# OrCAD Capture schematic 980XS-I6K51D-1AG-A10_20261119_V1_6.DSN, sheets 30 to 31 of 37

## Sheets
30 P0032_S3_USB/AUD/FLASH/XTAL: size A1
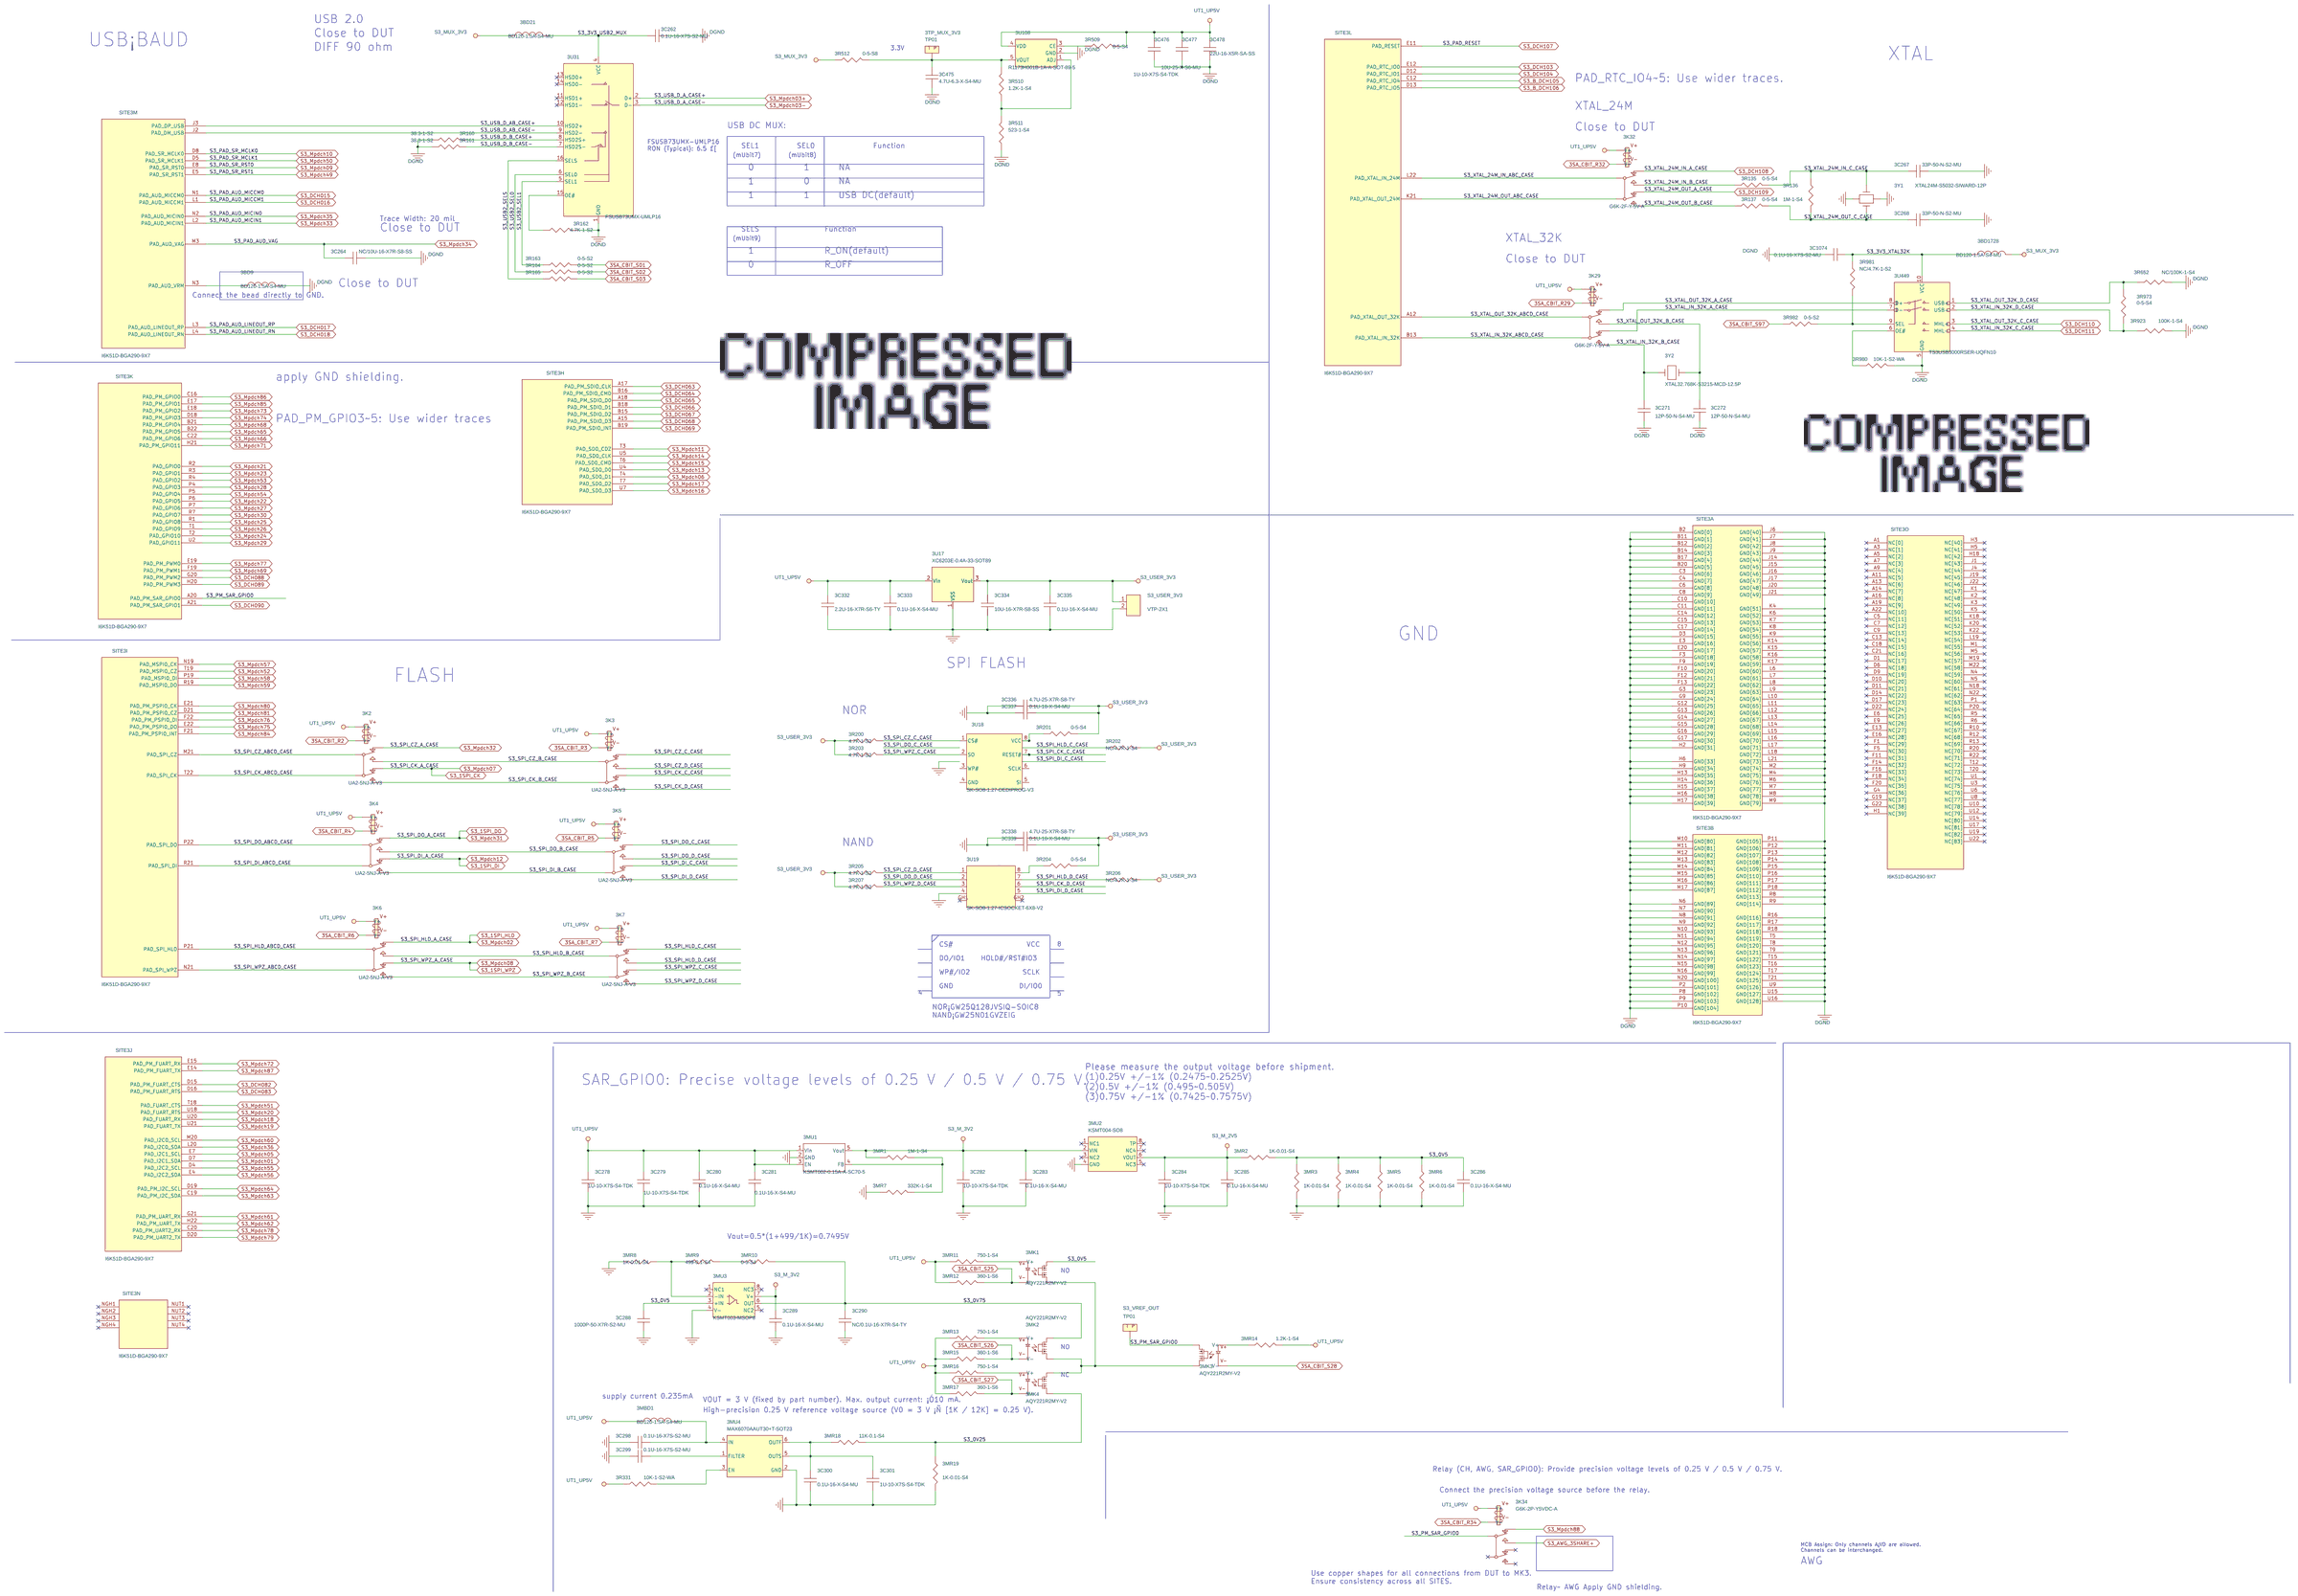
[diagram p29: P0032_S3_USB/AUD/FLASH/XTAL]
31 P0012_S1_USB/AUD/FLASH/XTAL: size A1
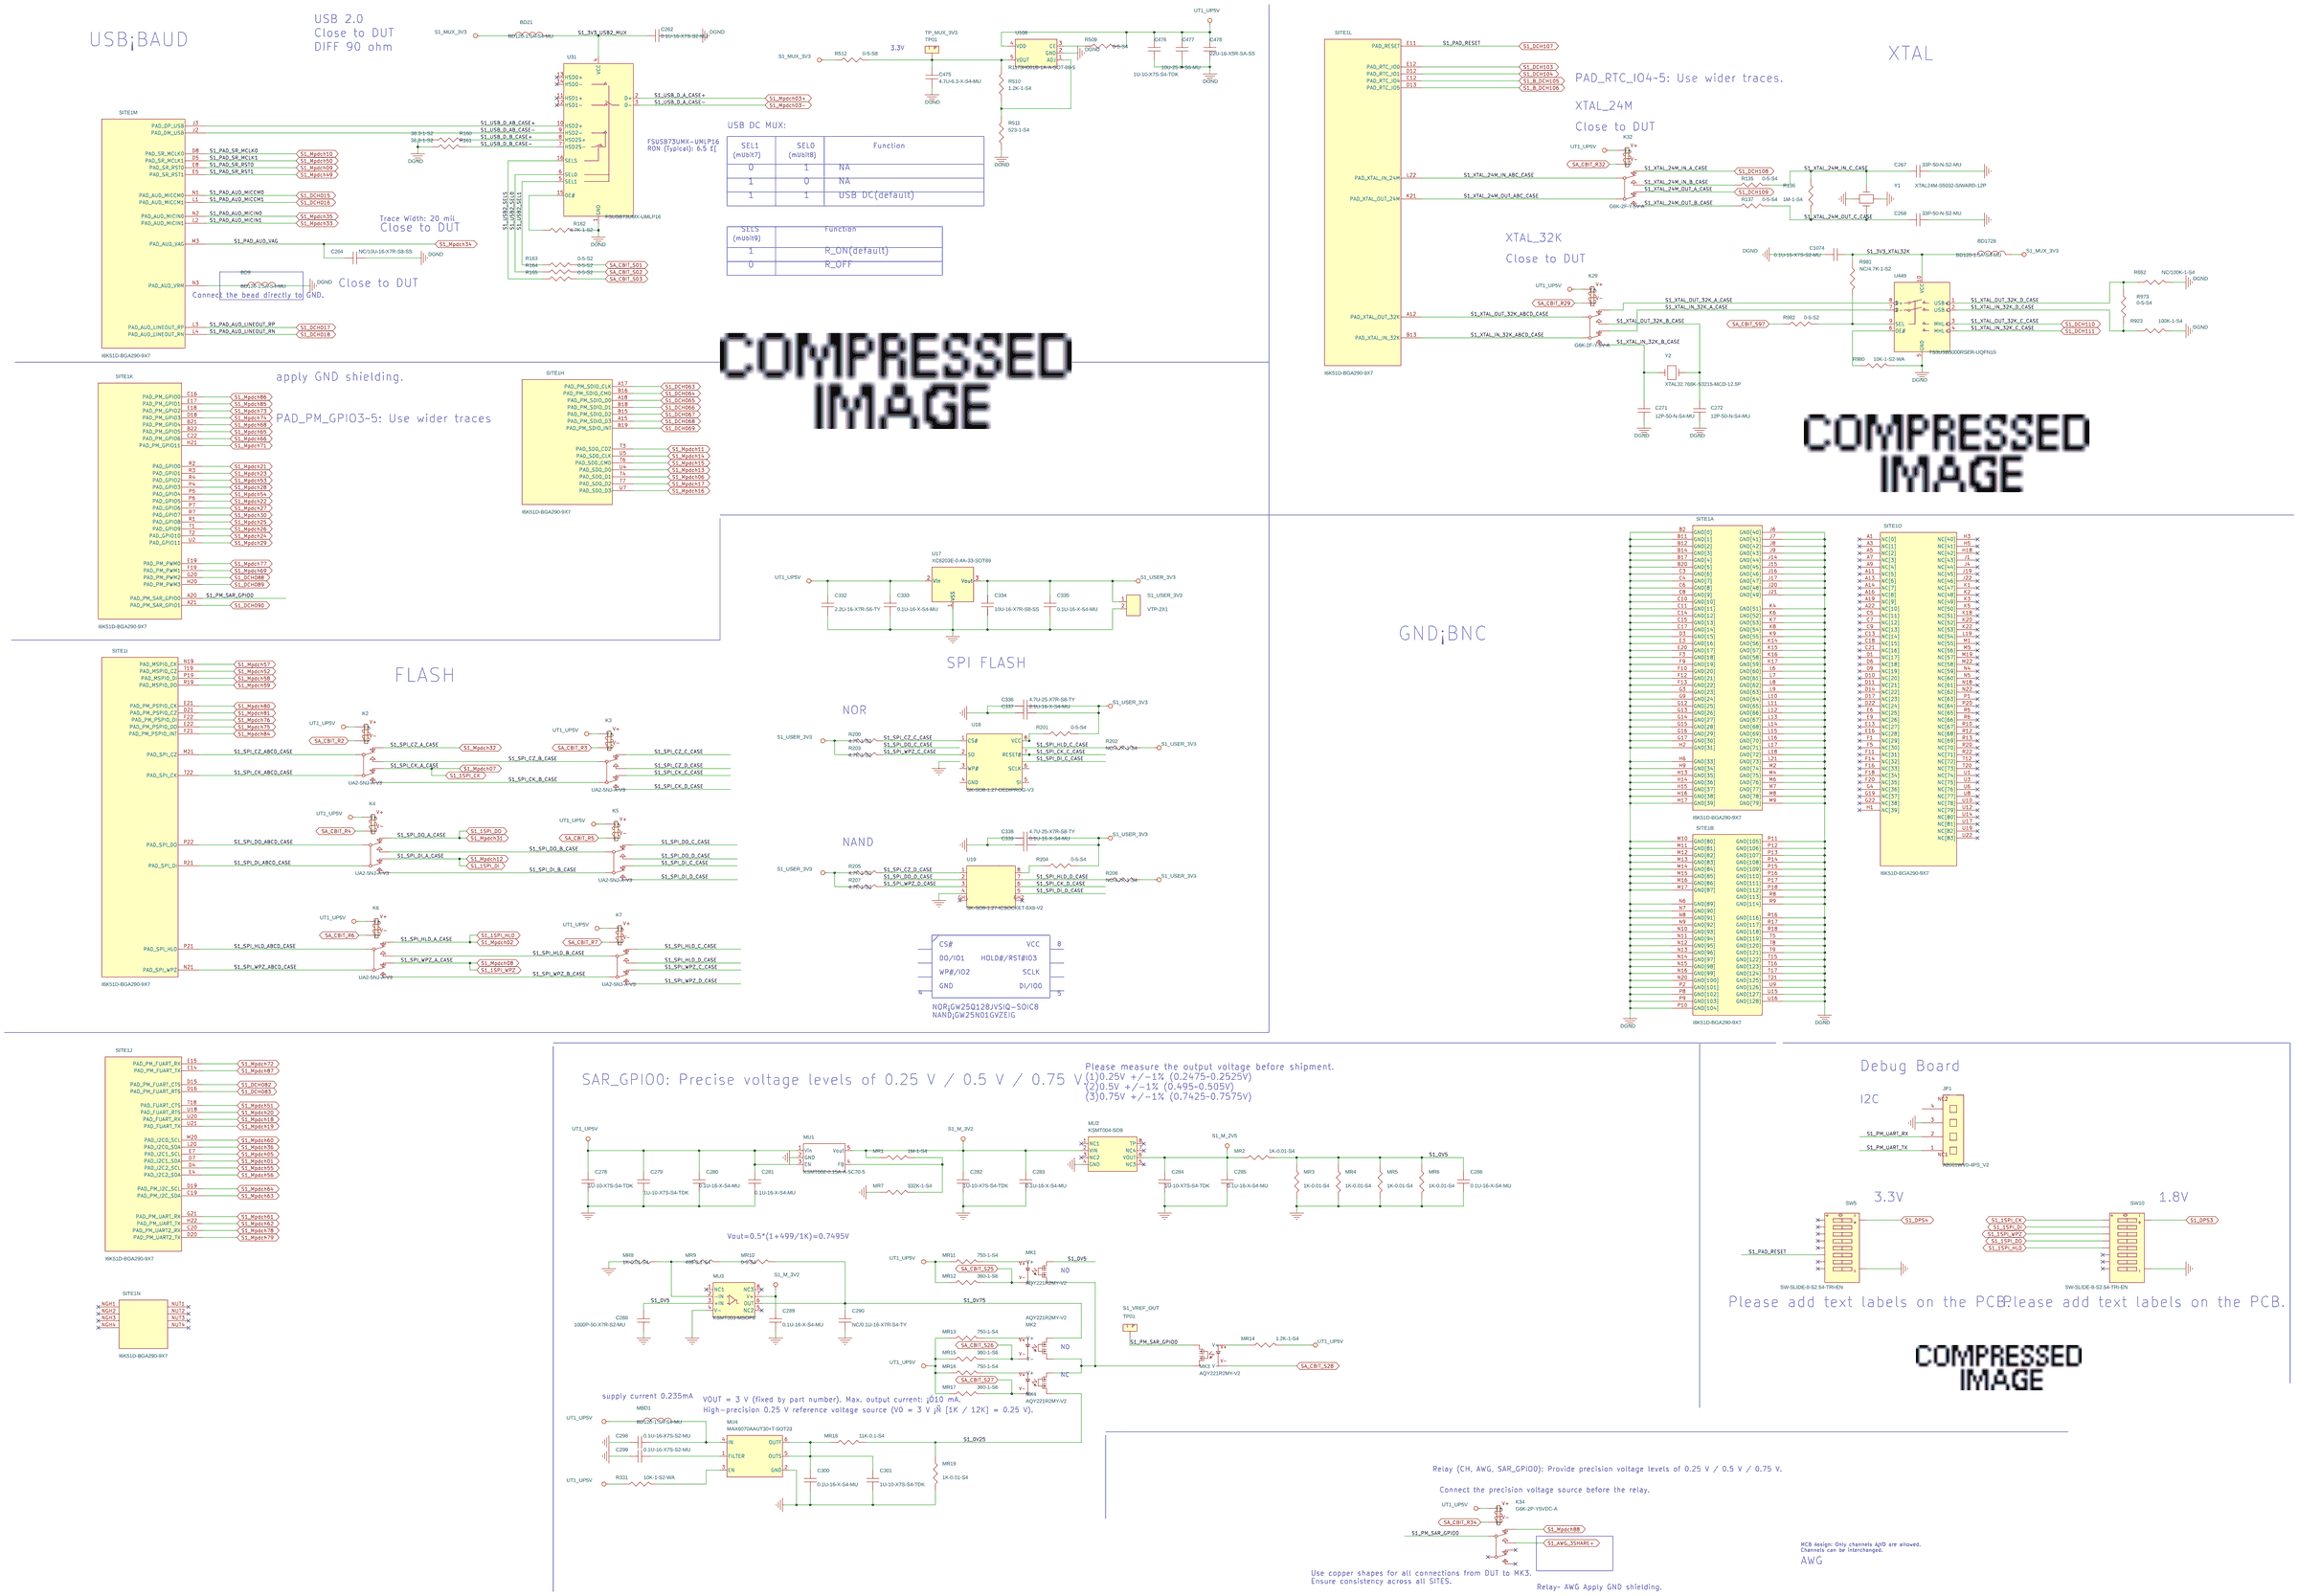
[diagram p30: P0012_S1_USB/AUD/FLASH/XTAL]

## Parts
sheet P0011_S1_POWER
SITE1  I6K51D-BGA290-9X7  [SK_TFBGA7X9_290P_0P4MM_JG]  (sections A,B,C,D,E,F,G,H,I,J,K,L,M,N,O)
sheet P0012_S1_USB/AUD/FLASH/XTAL
BD9  BD120-1.5A-S4-MU  [FB0402]
BD21  BD120-1.5A-S4-MU  [FB0402]
BD1728  BD120-1.5A-S4-MU  [FB0402]
C262  0.1U-16-X7S-S2-MU  [C0201]
C264  NC/10U-16-X7R-S8-SS  [C0805]
C267  33P-50-N-S2-MU  [C0201]
C268  33P-50-N-S2-MU  [C0201]
C271  12P-50-N-S4-MU  [C0402]
C272  12P-50-N-S4-MU  [C0402]
C278  1U-10-X7S-S4-TDK  [C0402]
C279  1U-10-X7S-S4-TDK  [C0402]
C280  0.1U-16-X-S4-MU  [C0402]
C281  0.1U-16-X-S4-MU  [C0402]
C282  1U-10-X7S-S4-TDK  [C0402]
C283  0.1U-16-X-S4-MU  [C0402]
C284  1U-10-X7S-S4-TDK  [C0402]
C285  0.1U-16-X-S4-MU  [C0402]
C286  0.1U-16-X-S4-MU  [C0402]
C288  1000P-50-X7R-S2-MU  [C0201]
C289  0.1U-16-X-S4-MU  [C0402]
C290  NC/0.1U-16-X7R-S4-TY  [C0402]
C298  0.1U-16-X7S-S2-MU  [C0201]
C299  0.1U-16-X7S-S2-MU  [C0201]
C300  0.1U-16-X-S4-MU  [C0402]
C301  1U-10-X7S-S4-TDK  [C0402]
C332  2.2U-16-X7R-S6-TY  [C0603]
C333  0.1U-16-X-S4-MU  [C0402]
C334  10U-16-X7R-S8-SS  [C0805]
C335  0.1U-16-X-S4-MU  [C0402]
C336  4.7U-25-X7R-S8-TY  [C0805]
C337  0.1U-16-X-S4-MU  [C0402]
C338  4.7U-25-X7R-S8-TY  [C0805]
C339  0.1U-16-X-S4-MU  [C0402]
C475  4.7U-6.3-X-S4-MU  [C0402]
C476  1U-10-X7S-S4-TDK  [C0402]
C477  10U-25-X-S6-MU  [C0603]
C478  22U-16-X5R-SA-SS  [C1206]
C1074  0.1U-16-X7S-S2-MU  [C0201_MINI]
JP1  A2001WV0-4PS_V2  [CONN_S4X1_2MM_JWT]
K2  UA2-5NJ-A-V3  [RL_NECUA2_5V_V3]
K3  UA2-5NJ-A-V3  [RL_NECUA2_5V_V3]
K4  UA2-5NJ-A-V3  [RL_NECUA2_5V_V3]
K5  UA2-5NJ-A-V3  [RL_NECUA2_5V_V3]
K6  UA2-5NJ-A-V3  [RL_NECUA2_5V_V3]
K7  UA2-5NJ-A-V3  [RL_NECUA2_5V_V3]
K29  G6K-2F-Y-5V-A  [RL_G6K2F-Y_5V_OMRON]
K32  G6K-2F-Y-5V-A  [RL_G6K2F-Y_5V_OMRON]
K34  G6K-2P-Y5VDC-A  [RL_OMRONG6K2PY_5V]
MBD1  BD120-1.5A-S4-MU  [FB0402]
MK1  AQY221R2MY-V2  [RL_AQY221R2MY_5V_V2]
MK2  AQY221R2MY-V2  [RL_AQY221R2MY_5V_V2]
MK3  AQY221R2MY-V2  [RL_AQY221R2MY_5V_V2]
MK4  AQY221R2MY-V2  [RL_AQY221R2MY_5V_V2]
MR1  1M-1-S4  [R0402_UNBGA_V2]
MR2  1K-0.01-S4  [R0402_UNBGA_V2]
MR3  1K-0.01-S4  [R0402_UNBGA_V2]
MR4  1K-0.01-S4  [R0402_UNBGA_V2]
MR5  1K-0.01-S4  [R0402_UNBGA_V2]
MR6  1K-0.01-S4  [R0402_UNBGA_V2]
MR7  332K-1-S4  [R0402_UNBGA_V2]
MR8  1K-0.01-S4  [R0402_UNBGA_V2]
MR9  499-0.1-S4  [R0402]
MR10  0-5-S4  [R0402]
MR11  750-1-S4  [R0402]
MR12  360-1-S6  [R0603]
MR13  750-1-S4  [R0402]
MR14  1.2K-1-S4  [R0402]
MR15  360-1-S6  [R0603]
MR16  750-1-S4  [R0402]
MR17  360-1-S6  [R0603]
MR18  11K-0.1-S4  [R0402]
MR19  1K-0.01-S4  [R0402_UNBGA_V2]
MU1  KSMT002-0.15A-A-SC70-5  [SC70_5P]
MU2  KSMT004-SO8  [SO8_244X127MM]
MU3  KSMT003-MSOP8  [SO8_172X0P65MM]
MU4  MAX6070AAUT30+T-SOT23  [SOT23_6P_0P95X2P7MM_H1P45MM]
R135  0-5-S4  [R0402]
R136  1M-1-S4  [R0402]
R137  0-5-S4  [R0402]
R160  38.3-1-S2  [R0201_MINI]
R161  38.3-1-S2  [R0201_MINI]
R162  4.7K-1-S2  [R0201_MINI]
R163  0-5-S2  [R0201_MINI]
R164  0-5-S2  [R0201_MINI]
R165  0-5-S2  [R0201_MINI]
R200  4.7K-1-S2  [R0201]
R201  0-5-S4  [R0402]
R202  NC/4.7K-1-S4  [R0402]
R203  4.7K-1-S2  [R0201]
R204  0-5-S4  [R0402]
R205  4.7K-1-S2  [R0201]
R206  NC/4.7K-1-S4  [R0402]
R207  4.7K-1-S2  [R0201]
R331  10K-1-S2-WA  [R0201]
R509  0-5-S4  [R0402]
R510  1.2K-1-S4  [R0402]
R511  523-1-S4  [R0402]
R512  0-5-S8  [R0805]
R652  NC/100K-1-S4  [R0402]
R923  100K-1-S4  [R0402]
R973  0-5-S4  [R0402]
R980  10K-1-S2-WA  [R0201]
R981  NC/4.7K-1-S2  [R0201]
R982  0-5-S2  [R0201]
S1_USER_3V3  VTP-2X1  [VTP_2P_100]
S1_VREF_OUT  TP01  [TP_040_T]
SW5  SW-SLIDE-8-S2.54-TRI-EN  [SW_8PX1_2P54MM_SMD]
SW10  SW-SLIDE-8-S2.54-TRI-EN  [SW_8PX1_2P54MM_SMD]
TP_MUX_3V3  TP01  [TP_040_T]
U17  XC6203E-0.4A-33-SOT89  [SOT89]
U18  SK-SO8-1.27-DEDIPROG-V3  [SK_SO8_1P27MM_DEDIPROG_V3]
U19  SK-SO8-1.27-ICSOCKET-6X8-V2  [SK_SO8_1P27MM_SDQ54CBAA_V2]
U31  FSUSB73UMX-UMLP16  [SW_UMLP2P6X1P8_12P_0P4MM]
U108  R1173H001B-1A-A-SOT-89-5  [SOT_89_5]
U449  TS3USB3000RSER-UQFN10  [UQFN2P05X1P55_10P_0P5MM]
Y1  XTAL24M-S5032-SIWARD-12P  [XTAL_S_DUAL1]
Y2  XTAL32.768K-S3215-MCD-12.5P  [XTAL_3P2X1P5MM_2P_MC]
sheet P0032_S3_USB/AUD/FLASH/XTAL
3BD9  BD120-1.5A-S4-MU  [FB0402]
3BD21  BD120-1.5A-S4-MU  [FB0402]
3BD1728  BD120-1.5A-S4-MU  [FB0402]
3C262  0.1U-16-X7S-S2-MU  [C0201]
3C264  NC/10U-16-X7R-S8-SS  [C0805]
3C267  33P-50-N-S2-MU  [C0201]
3C268  33P-50-N-S2-MU  [C0201]
3C271  12P-50-N-S4-MU  [C0402]
3C272  12P-50-N-S4-MU  [C0402]
3C278  1U-10-X7S-S4-TDK  [C0402]
3C279  1U-10-X7S-S4-TDK  [C0402]
3C280  0.1U-16-X-S4-MU  [C0402]
3C281  0.1U-16-X-S4-MU  [C0402]
3C282  1U-10-X7S-S4-TDK  [C0402]
3C283  0.1U-16-X-S4-MU  [C0402]
3C284  1U-10-X7S-S4-TDK  [C0402]
3C285  0.1U-16-X-S4-MU  [C0402]
3C286  0.1U-16-X-S4-MU  [C0402]
3C288  1000P-50-X7R-S2-MU  [C0201]
3C289  0.1U-16-X-S4-MU  [C0402]
3C290  NC/0.1U-16-X7R-S4-TY  [C0402]
3C298  0.1U-16-X7S-S2-MU  [C0201]
3C299  0.1U-16-X7S-S2-MU  [C0201]
3C300  0.1U-16-X-S4-MU  [C0402]
3C301  1U-10-X7S-S4-TDK  [C0402]
3C332  2.2U-16-X7R-S6-TY  [C0603]
3C333  0.1U-16-X-S4-MU  [C0402]
3C334  10U-16-X7R-S8-SS  [C0805]
3C335  0.1U-16-X-S4-MU  [C0402]
3C336  4.7U-25-X7R-S8-TY  [C0805]
3C337  0.1U-16-X-S4-MU  [C0402]
3C338  4.7U-25-X7R-S8-TY  [C0805]
3C339  0.1U-16-X-S4-MU  [C0402]
3C475  4.7U-6.3-X-S4-MU  [C0402]
3C476  1U-10-X7S-S4-TDK  [C0402]
3C477  10U-25-X-S6-MU  [C0603]
3C478  22U-16-X5R-SA-SS  [C1206]
3C1074  0.1U-16-X7S-S2-MU  [C0201_MINI]
3K2  UA2-5NJ-A-V3  [RL_NECUA2_5V_V3]
3K3  UA2-5NJ-A-V3  [RL_NECUA2_5V_V3]
3K4  UA2-5NJ-A-V3  [RL_NECUA2_5V_V3]
3K5  UA2-5NJ-A-V3  [RL_NECUA2_5V_V3]
3K6  UA2-5NJ-A-V3  [RL_NECUA2_5V_V3]
3K7  UA2-5NJ-A-V3  [RL_NECUA2_5V_V3]
3K29  G6K-2F-Y-5V-A  [RL_G6K2F-Y_5V_OMRON]
3K32  G6K-2F-Y-5V-A  [RL_G6K2F-Y_5V_OMRON]
3K34  G6K-2P-Y5VDC-A  [RL_OMRONG6K2PY_5V]
3MBD1  BD120-1.5A-S4-MU  [FB0402]
3MK1  AQY221R2MY-V2  [RL_AQY221R2MY_5V_V2]
3MK2  AQY221R2MY-V2  [RL_AQY221R2MY_5V_V2]
3MK3  AQY221R2MY-V2  [RL_AQY221R2MY_5V_V2]
3MK4  AQY221R2MY-V2  [RL_AQY221R2MY_5V_V2]
3MR1  1M-1-S4  [R0402_UNBGA_V2]
3MR2  1K-0.01-S4  [R0402_UNBGA_V2]
3MR3  1K-0.01-S4  [R0402_UNBGA_V2]
3MR4  1K-0.01-S4  [R0402_UNBGA_V2]
3MR5  1K-0.01-S4  [R0402_UNBGA_V2]
3MR6  1K-0.01-S4  [R0402_UNBGA_V2]
3MR7  332K-1-S4  [R0402_UNBGA_V2]
3MR8  1K-0.01-S4  [R0402_UNBGA_V2]
3MR9  499-0.1-S4  [R0402]
3MR10  0-5-S4  [R0402]
3MR11  750-1-S4  [R0402]
3MR12  360-1-S6  [R0603]
3MR13  750-1-S4  [R0402]
3MR14  1.2K-1-S4  [R0402]
3MR15  360-1-S6  [R0603]
3MR16  750-1-S4  [R0402]
3MR17  360-1-S6  [R0603]
3MR18  11K-0.1-S4  [R0402]
3MR19  1K-0.01-S4  [R0402_UNBGA_V2]
3MU1  KSMT002-0.15A-A-SC70-5  [SC70_5P]
3MU2  KSMT004-SO8  [SO8_244X127MM]
3MU3  KSMT003-MSOP8  [SO8_172X0P65MM]
3MU4  MAX6070AAUT30+T-SOT23  [SOT23_6P_0P95X2P7MM_H1P45MM]
3R135  0-5-S4  [R0402]
3R136  1M-1-S4  [R0402]
3R137  0-5-S4  [R0402]
3R160  38.3-1-S2  [R0201_MINI]
3R161  38.3-1-S2  [R0201_MINI]
3R162  4.7K-1-S2  [R0201_MINI]
3R163  0-5-S2  [R0201_MINI]
3R164  0-5-S2  [R0201_MINI]
3R165  0-5-S2  [R0201_MINI]
3R200  4.7K-1-S2  [R0201]
3R201  0-5-S4  [R0402]
3R202  NC/4.7K-1-S4  [R0402]
3R203  4.7K-1-S2  [R0201]
3R204  0-5-S4  [R0402]
3R205  4.7K-1-S2  [R0201]
3R206  NC/4.7K-1-S4  [R0402]
3R207  4.7K-1-S2  [R0201]
3R331  10K-1-S2-WA  [R0201]
3R509  0-5-S4  [R0402]
3R510  1.2K-1-S4  [R0402]
3R511  523-1-S4  [R0402]
3R512  0-5-S8  [R0805]
3R652  NC/100K-1-S4  [R0402]
3R923  100K-1-S4  [R0402]
3R973  0-5-S4  [R0402]
3R980  10K-1-S2-WA  [R0201]
3R981  NC/4.7K-1-S2  [R0201]
3R982  0-5-S2  [R0201]
3TP_MUX_3V3  TP01  [TP_040_T]
3U17  XC6203E-0.4A-33-SOT89  [SOT89]
3U18  SK-SO8-1.27-DEDIPROG-V3  [SK_SO8_1P27MM_DEDIPROG_V3]
3U19  SK-SO8-1.27-ICSOCKET-6X8-V2  [SK_SO8_1P27MM_SDQ54CBAA_V2]
3U31  FSUSB73UMX-UMLP16  [SW_UMLP2P6X1P8_12P_0P4MM]
3U108  R1173H001B-1A-A-SOT-89-5  [SOT_89_5]
3U449  TS3USB3000RSER-UQFN10  [UQFN2P05X1P55_10P_0P5MM]
3Y1  XTAL24M-S5032-SIWARD-12P  [XTAL_S_DUAL1]
3Y2  XTAL32.768K-S3215-MCD-12.5P  [XTAL_3P2X1P5MM_2P_MC]
S3_USER_3V3  VTP-2X1  [VTP_2P_100]
S3_VREF_OUT  TP01  [TP_040_T]
SITE3  I6K51D-BGA290-9X7  [SK_TFBGA7X9_290P_0P4MM_JG]  (sections A,B,C,D,E,F,G,H,I,J,K,L,M,N,O)

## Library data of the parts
SITE1 SITE3 = I6K51D-BGA290-9X7
BD9 BD21 MBD1 = BD120-1.5A-S4-MU
3BD21 3BD1728 BD1728 = BD120-1.5A-S4-MU: KAIROSNAME: BD21
3C262 C262 C298 C299 = 0.1U-16-X7S-S2-MU
3C334 C264 C334 = 10U-16-X7R-S8-SS
C267 C268 = 33P-50-N-S2-MU
C271 C272 = 12P-50-N-S4-MU
C278 C279 C282 C284 C301 = 1U-10-X7S-S4-TDK
3C333 3C335 3C337 3C339 C280 C281 C283 C285 C286 C289 C290 C300 C333 C335 C337 C339 = 0.1U-16-X-S4-MU
C288 = 1000P-50-X7R-S2-MU
3C332 C332 = 2.2U-16-X7R-S6-TY
3C336 3C338 C336 C338 = 4.7U-25-X7R-S8-TY
C475 = 4.7U-6.3-X-S4-MU
C476 = 1U-10-X-S4-MU
C477 = 10U-25-X-S6-MU
C478 = 22U-16-X5R-SA-SS
3C1074 C1074 = 0.1U-16-X7S-S2-MU: KAIROSNAME: C262
JP1 = A2001WV0-4PS_V2
3K2-3K7 K2-K7 = UA2-5NJ-A-V3
K29 K32 = G6K-2F-Y-5V-A
K34 = G6K-2P-Y5VDC-A
MK1-MK4 = AQY221R2MY-V2
MR1 R136 = 1M-1-S4
MR2-MR6 MR8 MR19 = 1K-0.01-S4
MR7 = 332K-1-S4
MR9 = 499-0.1-S4
3R201 3R204 3R973 MR10 R135 R137 R201 R204 R509 R973 = 0-5-S4
MR11 MR13 MR16 = 750-1-S4
MR12 MR15 MR17 = 360-1-S4
MR14 R510 = 1.2K-1-S4
MR18 = 11K-0.1-S4
MU1 = KSMT002-0.15A-A-SC70-5
MU2 = KSMT004-SO8
MU3 = KSMT003-MSOP8
MU4 = MAX6070AAUT30+T-SOT23
R160 R161 = 38.3-1-S2
3R200 3R202 3R203 3R205-3R207 3R981 R162 R200 R202 R203 R205-R207 R981 = 4.7K-1-S2
3R982 R163-R165 R982 = 0-5-S2
3R980 R331 R980 = 10K-1-S2-WA
R511 = 523-1-S4
R512 = 0-5-S8
3R652 3R923 R652 R923 = 100K-1-S4
S1_USER_3V3 S3_USER_3V3 = VTP-2X1
S1_VREF_OUT = TP01
SW5 = SW-SLIDE-8-S2.54-TRI-EN
SW10 = SW-SLIDE-8-S2.54-TRI-EN: KAIROSNAME: SW5
TP_MUX_3V3 = TP03-D
3U17 U17 = XC6203E-0.4A-33-SOT89
3U18 U18 = SK-SO8-1.27-DEDIPROG-V3
3U19 U19 = SK-SO8-1.27-ICSOCKET-6X8-V2
U31 = FSUSB73UMX-UMLP16
U108 = R1173H001B-1A-A-SOT-89-5
3U449 U449 = TS3USB3000RSER-UQFN10
Y1 = XTAL24M-S5032-SIWARD-12P
Y2 = XTAL32.768K-S3215-MCD-12.5P
3BD9 = BD120-1.5A-S4-MU: KAIROSNAME: BD9
3C264 = 10U-16-X7R-S8-SS: KAIROSNAME: C264
3C267 = 33P-50-N-S2-MU: KAIROSNAME: C267
3C268 = 33P-50-N-S2-MU: KAIROSNAME: C268
3C271 = 12P-50-N-S4-MU: KAIROSNAME: C271
3C272 = 12P-50-N-S4-MU: KAIROSNAME: C272
3C278 = 1U-10-X7S-S4-TDK: KAIROSNAME: C278
3C279 = 1U-10-X7S-S4-TDK: KAIROSNAME: C279
3C280 = 0.1U-16-X-S4-MU: KAIROSNAME: C280
3C281 = 0.1U-16-X-S4-MU: KAIROSNAME: C281
3C282 = 1U-10-X7S-S4-TDK: KAIROSNAME: C282
3C283 = 0.1U-16-X-S4-MU: KAIROSNAME: C283
3C284 = 1U-10-X7S-S4-TDK: KAIROSNAME: C284
3C285 = 0.1U-16-X-S4-MU: KAIROSNAME: C285
3C286 = 0.1U-16-X-S4-MU: KAIROSNAME: C286
3C288 = 1000P-50-X7R-S2-MU: KAIROSNAME: C288
3C289 = 0.1U-16-X-S4-MU: KAIROSNAME: C289
3C290 = 0.1U-16-X-S4-MU: KAIROSNAME: C290
3C298 = 0.1U-16-X7S-S2-MU: KAIROSNAME: C298
3C299 = 0.1U-16-X7S-S2-MU: KAIROSNAME: C299
3C300 = 0.1U-16-X-S4-MU: KAIROSNAME: C300
3C301 = 1U-10-X7S-S4-TDK: KAIROSNAME: C301
3C475 = 4.7U-6.3-X-S4-MU: KAIROSNAME: C475
3C476 = 1U-10-X-S4-MU: KAIROSNAME: C476
3C477 = 10U-25-X-S6-MU: KAIROSNAME: C477
3C478 = 22U-16-X5R-SA-SS: KAIROSNAME: C478
3K29 = G6K-2F-Y-5V-A: KAIROSNAME: K29
3K32 = G6K-2F-Y-5V-A: KAIROSNAME: K32
3K34 = G6K-2P-Y5VDC-A: KAIROSNAME: K34
3MBD1 = BD120-1.5A-S4-MU: KAIROSNAME: MBD1
3MK1 = AQY221R2MY-V2: KAIROSNAME: MK1
3MK2 = AQY221R2MY-V2: KAIROSNAME: MK2
3MK3 = AQY221R2MY-V2: KAIROSNAME: MK3
3MK4 = AQY221R2MY-V2: KAIROSNAME: MK4
3MR1 = 1M-1-S4: KAIROSNAME: MR1
3MR2 = 1K-0.01-S4: KAIROSNAME: MR2
3MR3 = 1K-0.01-S4: KAIROSNAME: MR3
3MR4 = 1K-0.01-S4: KAIROSNAME: MR4
3MR5 = 1K-0.01-S4: KAIROSNAME: MR5
3MR6 = 1K-0.01-S4: KAIROSNAME: MR6
3MR7 = 332K-1-S4: KAIROSNAME: MR7
3MR8 = 1K-0.01-S4: KAIROSNAME: MR8
3MR9 = 499-0.1-S4: KAIROSNAME: MR9
3MR10 = 0-5-S4: KAIROSNAME: MR10
3MR11 = 750-1-S4: KAIROSNAME: MR11
3MR12 = 360-1-S4: KAIROSNAME: MR12
3MR13 = 750-1-S4: KAIROSNAME: MR13
3MR14 = 1.2K-1-S4: KAIROSNAME: MR14
3MR15 = 360-1-S4: KAIROSNAME: MR15
3MR16 = 750-1-S4: KAIROSNAME: MR16
3MR17 = 360-1-S4: KAIROSNAME: MR17
3MR18 = 11K-0.1-S4: KAIROSNAME: MR18
3MR19 = 1K-0.01-S4: KAIROSNAME: MR19
3MU1 = KSMT002-0.15A-A-SC70-5: KAIROSNAME: MU1
3MU2 = KSMT004-SO8: KAIROSNAME: MU2
3MU3 = KSMT003-MSOP8: KAIROSNAME: MU3
3MU4 = MAX6070AAUT30+T-SOT23: KAIROSNAME: MU4
3R135 = 0-5-S4: KAIROSNAME: R135
3R136 = 1M-1-S4: KAIROSNAME: R136
3R137 = 0-5-S4: KAIROSNAME: R137
3R160 = 38.3-1-S2: KAIROSNAME: R160
3R161 = 38.3-1-S2: KAIROSNAME: R161
3R162 = 4.7K-1-S2: KAIROSNAME: R162
3R163 = 0-5-S2: KAIROSNAME: R163
3R164 = 0-5-S2: KAIROSNAME: R164
3R165 = 0-5-S2: KAIROSNAME: R165
3R331 = 10K-1-S2-WA: KAIROSNAME: R331
3R509 = 0-5-S4: KAIROSNAME: R509
3R510 = 1.2K-1-S4: KAIROSNAME: R510
3R511 = 523-1-S4: KAIROSNAME: R511
3R512 = 0-5-S8: KAIROSNAME: R512
3TP_MUX_3V3 = TP03-D: KAIROSNAME: TP_MUX_3V3
3U31 = FSUSB73UMX-UMLP16: KAIROSNAME: U31
3U108 = R1173H001B-1A-A-SOT-89-5: KAIROSNAME: U108
3Y1 = XTAL24M-S5032-SIWARD-12P: KAIROSNAME: Y1
3Y2 = XTAL32.768K-S3215-MCD-12.5P: KAIROSNAME: Y2
S3_VREF_OUT = TP01: KAIROSNAME: S1_VREF_OUT

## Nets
DGND: 3BD9.2 3C262.2 3C264.2 3C267.2 3C268.2 3C271.2 3C272.2 3C278.2 3C279.2 3C280.2 3C281.2 3C282.2 3C283.2 3C284.2 3C285.2 3C286.2 3C288.2 3C289.2 3C290.2 3C298.1 3C299.1 3C300.2 3C301.2 3C332.2 3C333.2 3C334.2 3C335.2 3C336.1 3C337.1 3C338.1 3C339.1 3C475.2 3C476.2 3C477.2 3C478.2 3C1074.2 3MR3.2 3MR4.2 3MR5.2 3MR6.2 3MR7.1 3MR8.2 3MR19.2 3MU1.2(GND) 3MU2.4(GND) 3MU3.4(V-) 3MU4.2(GND) 3R160.1 3R161.1 3R162.2 3R511.2 3R652.2 3R923.2 3R980.2 3U17.1(VSS) 3U19.4 3U31.1(GND) 3U108.2(GND) 3U449.5(GND) 3Y1.2 3Y1.4 BD9.2 C262.2 C264.2 C267.2 C268.2 C271.2 C272.2 C278.2 C279.2 C280.2 C281.2 C282.2 C283.2 C284.2 C285.2 C286.2 C288.2 C289.2 C290.2 C298.1 C299.1 C300.2 C301.2 C332.2 C333.2 C334.2 C335.2 C336.1 C337.1 C338.1 C339.1 C475.2 C476.2 C477.2 C478.2 C1074.2 JP1.3 MR3.2 MR4.2 MR5.2 MR6.2 MR7.1 MR8.2 MR19.2 MU1.2(GND) MU2.4(GND) MU3.4(V-) MU4.2(GND) R160.1 R161.1 R162.2 R511.2 R652.2 R923.2 R980.2 S1_USER_3V3.2 S3_USER_3V3.2 SITE1.B2(GND[0]) SITE1.B11(GND[1]) SITE1.B12(GND[2]) SITE1.B14(GND[3]) SITE1.B17(GND[4]) SITE1.B20(GND[5]) SITE1.C3(GND[6]) SITE1.C4(GND[7]) SITE1.C6(GND[8]) SITE1.C8(GND[9]) SITE1.C10(GND[10]) SITE1.C11(GND[11]) SITE1.C14(GND[12]) SITE1.C15(GND[13]) SITE1.C17(GND[14]) SITE1.D3(GND[15]) SITE1.E3(GND[16]) SITE1.E20(GND[17]) SITE1.F3(GND[18]) SITE1.F9(GND[19]) SITE1.F10(GND[20]) SITE1.F12(GND[21]) SITE1.F13(GND[22]) SITE1.G3(GND[23]) SITE1.G9(GND[24]) SITE1.G12(GND[25]) SITE1.G13(GND[26]) SITE1.G14(GND[27]) SITE1.G15(GND[28]) SITE1.G16(GND[29]) SITE1.G17(GND[30]) SITE1.H2(GND[31]) SITE1.H6(GND[33]) SITE1.H9(GND[34]) SITE1.H13(GND[35]) SITE1.H14(GND[36]) SITE1.H15(GND[37]) SITE1.H16(GND[38]) SITE1.H17(GND[39]) SITE1.J6(GND[40]) SITE1.J7(GND[41]) SITE1.J8(GND[42]) SITE1.J9(GND[43]) SITE1.J14(GND[44]) SITE1.J15(GND[45]) SITE1.J16(GND[46]) SITE1.J17(GND[47]) SITE1.J20(GND[48]) SITE1.J21(GND[49]) SITE1.K4(GND[51]) SITE1.K6(GND[52]) SITE1.K7(GND[53]) SITE1.K8(GND[54]) SITE1.K9(GND[55]) SITE1.K14(GND[56]) SITE1.K15(GND[57]) SITE1.K16(GND[58]) SITE1.K17(GND[59]) SITE1.L6(GND[60]) SITE1.L7(GND[61]) SITE1.L8(GND[62]) SITE1.L9(GND[63]) SITE1.L10(GND[64]) SITE1.L11(GND[65]) SITE1.L12(GND[66]) SITE1.L13(GND[67]) SITE1.L14(GND[68]) SITE1.L15(GND[69]) SITE1.L16(GND[70]) SITE1.L17(GND[71]) SITE1.L18(GND[72]) SITE1.L21(GND[73]) SITE1.M2(GND[74]) SITE1.M4(GND[75]) SITE1.M6(GND[76]) SITE1.M7(GND[77]) SITE1.M8(GND[78]) SITE1.M9(GND[79]) SITE1.M10(GND[80]) SITE1.M11(GND[81]) SITE1.M12(GND[82]) SITE1.M13(GND[83]) SITE1.M14(GND[84]) SITE1.M15(GND[85]) SITE1.M16(GND[86]) SITE1.M17(GND[87]) SITE1.N6(GND[89]) SITE1.N7(GND[90]) SITE1.N8(GND[91]) SITE1.N9(GND[92]) SITE1.N10(GND[93]) SITE1.N11(GND[94]) SITE1.N12(GND[95]) SITE1.N13(GND[96]) SITE1.N14(GND[97]) SITE1.N15(GND[98]) SITE1.N16(GND[99]) SITE1.N20(GND[100]) SITE1.P2(GND[101]) SITE1.P8(GND[102]) SITE1.P9(GND[103]) SITE1.P10(GND[104]) SITE1.P11(GND[105]) SITE1.P12(GND[106]) SITE1.P13(GND[107]) SITE1.P14(GND[108]) SITE1.P15(GND[109]) SITE1.P16(GND[110]) SITE1.P17(GND[111]) SITE1.P18(GND[112]) SITE1.R8(GND[113]) SITE1.R9(GND[114]) SITE1.R16(GND[116]) SITE1.R17(GND[117]) SITE1.R18(GND[118]) SITE1.T5(GND[119]) SITE1.T8(GND[120]) SITE1.T9(GND[121]) SITE1.T15(GND[122]) SITE1.T16(GND[123]) SITE1.T17(GND[124]) SITE1.T21(GND[125]) SITE1.U9(GND[126]) SITE1.U15(GND[127]) SITE1.U16(GND[128]) SITE3.B2(GND[0]) SITE3.B11(GND[1]) SITE3.B12(GND[2]) SITE3.B14(GND[3]) SITE3.B17(GND[4]) SITE3.B20(GND[5]) SITE3.C3(GND[6]) SITE3.C4(GND[7]) SITE3.C6(GND[8]) SITE3.C8(GND[9]) SITE3.C10(GND[10]) SITE3.C11(GND[11]) SITE3.C14(GND[12]) SITE3.C15(GND[13]) SITE3.C17(GND[14]) SITE3.D3(GND[15]) SITE3.E3(GND[16]) SITE3.E20(GND[17]) SITE3.F3(GND[18]) SITE3.F9(GND[19]) SITE3.F10(GND[20]) SITE3.F12(GND[21]) SITE3.F13(GND[22]) SITE3.G3(GND[23]) SITE3.G9(GND[24]) SITE3.G12(GND[25]) SITE3.G13(GND[26]) SITE3.G14(GND[27]) SITE3.G15(GND[28]) SITE3.G16(GND[29]) SITE3.G17(GND[30]) SITE3.H2(GND[31]) SITE3.H6(GND[33]) SITE3.H9(GND[34]) SITE3.H13(GND[35]) SITE3.H14(GND[36]) SITE3.H15(GND[37]) SITE3.H16(GND[38]) SITE3.H17(GND[39]) SITE3.J6(GND[40]) SITE3.J7(GND[41]) SITE3.J8(GND[42]) SITE3.J9(GND[43]) SITE3.J14(GND[44]) SITE3.J15(GND[45]) SITE3.J16(GND[46]) SITE3.J17(GND[47]) SITE3.J20(GND[48]) SITE3.J21(GND[49]) SITE3.K4(GND[51]) SITE3.K6(GND[52]) SITE3.K7(GND[53]) SITE3.K8(GND[54]) SITE3.K9(GND[55]) SITE3.K14(GND[56]) SITE3.K15(GND[57]) SITE3.K16(GND[58]) SITE3.K17(GND[59]) SITE3.L6(GND[60]) SITE3.L7(GND[61]) SITE3.L8(GND[62]) SITE3.L9(GND[63]) SITE3.L10(GND[64]) SITE3.L11(GND[65]) SITE3.L12(GND[66]) SITE3.L13(GND[67]) SITE3.L14(GND[68]) SITE3.L15(GND[69]) SITE3.L16(GND[70]) SITE3.L17(GND[71]) SITE3.L18(GND[72]) SITE3.L21(GND[73]) SITE3.M2(GND[74]) SITE3.M4(GND[75]) SITE3.M6(GND[76]) SITE3.M7(GND[77]) SITE3.M8(GND[78]) SITE3.M9(GND[79]) SITE3.M10(GND[80]) SITE3.M11(GND[81]) SITE3.M12(GND[82]) SITE3.M13(GND[83]) SITE3.M14(GND[84]) SITE3.M15(GND[85]) SITE3.M16(GND[86]) SITE3.M17(GND[87]) SITE3.N6(GND[89]) SITE3.N7(GND[90]) SITE3.N8(GND[91]) SITE3.N9(GND[92]) SITE3.N10(GND[93]) SITE3.N11(GND[94]) SITE3.N12(GND[95]) SITE3.N13(GND[96]) SITE3.N14(GND[97]) SITE3.N15(GND[98]) SITE3.N16(GND[99]) SITE3.N20(GND[100]) SITE3.P2(GND[101]) SITE3.P8(GND[102]) SITE3.P9(GND[103]) SITE3.P10(GND[104]) SITE3.P11(GND[105]) SITE3.P12(GND[106]) SITE3.P13(GND[107]) SITE3.P14(GND[108]) SITE3.P15(GND[109]) SITE3.P16(GND[110]) SITE3.P17(GND[111]) SITE3.P18(GND[112]) SITE3.R8(GND[113]) SITE3.R9(GND[114]) SITE3.R16(GND[116]) SITE3.R17(GND[117]) SITE3.R18(GND[118]) SITE3.T5(GND[119]) SITE3.T8(GND[120]) SITE3.T9(GND[121]) SITE3.T15(GND[122]) SITE3.T16(GND[123]) SITE3.T17(GND[124]) SITE3.T21(GND[125]) SITE3.U9(GND[126]) SITE3.U15(GND[127]) SITE3.U16(GND[128]) SW5.9 SW10.9 U17.1(VSS) U19.4 U31.1(GND) U108.2(GND) U449.5(GND) Y1.2 Y1.4 ; also on sheet 1 2 3 4 5 6 7 8 9 10 11 12 13 14 17 18 19 20 21 22 23 24 25 26 27 28 32 33 34 35 36 37
3SA_CBIT_R2: 3K2.8(V-)
3SA_CBIT_R3: 3K3.8(V-)
3SA_CBIT_R4: 3K4.8(V-)
3SA_CBIT_R5: 3K5.8(V-)
3SA_CBIT_R6: 3K6.8(V-)
3SA_CBIT_R7: 3K7.8(V-)
3SA_CBIT_R29: 3K29.8(V-)
3SA_CBIT_R32: 3K32.8(V-)
3SA_CBIT_R34: 3K34.8(V-)
3SA_CBIT_S01: 3R163.1
3SA_CBIT_S02: 3R164.1
3SA_CBIT_S03: 3R165.1
3SA_CBIT_S25: 3MK1.2(V-) 3MR12.2
3SA_CBIT_S26: 3MK2.2(V-) 3MR15.2
3SA_CBIT_S27: 3MK4.2(V-) 3MR17.2
3SA_CBIT_S28: 3MK3.2(V-)
3SA_CBIT_S97: 3R982.1
S1_0V5: C286.1 C288.1 MK1.4 MR2.2 MR3.1 MR4.1 MR5.1 MR6.1 MU3.3(+IN)
S1_0V25: MK4.3 MR18.2 MR19.1
S1_0V75: C290.1 MK2.4 MR10.2 MU3.6(OUT)
S1_1SPI_CK: K2.7 SW10.1
S1_1SPI_DI: K4.7 SW10.2
S1_1SPI_DO: K4.2 SW10.4
S1_1SPI_HLD: K6.2 SW10.5
S1_1SPI_WPZ: K6.7 SW10.3
S1_3V3_USB2_MUX: BD21.2 C262.1 U31.4(VCC)
S1_3V3_XTAL32K: BD1728.2 C1074.1 R981.1 U449.10(VCC)
S1_AWG_3SHARE+: K34.4 ; also on sheet 20
S1_B_DCH105: SITE1.C12(PAD_RTC_IO4)
S1_B_DCH106: SITE1.D13(PAD_RTC_IO5)
S1_DCH015: SITE1.N1(PAD_AUD_MICCM0)
S1_DCH016: SITE1.L1(PAD_AUD_MICCM1)
S1_DCH017: SITE1.L3(PAD_AUD_LINEOUT_RP)
S1_DCH018: SITE1.L4(PAD_AUD_LINEOUT_RN)
S1_DCH063: SITE1.A17(PAD_PM_SDIO_CLK)
S1_DCH064: SITE1.B16(PAD_PM_SDIO_CMD)
S1_DCH065: SITE1.A18(PAD_PM_SDIO_D0)
S1_DCH066: SITE1.B18(PAD_PM_SDIO_D1)
S1_DCH067: SITE1.B15(PAD_PM_SDIO_D2)
S1_DCH068: SITE1.A15(PAD_PM_SDIO_D3)
S1_DCH069: SITE1.B19(PAD_PM_SDIO_INT)
S1_DCH082: SITE1.D15(PAD_PM_FUART_CTS)
S1_DCH083: SITE1.D16(PAD_PM_FUART_RTS)
S1_DCH088: SITE1.G20(PAD_PM_PWM2)
S1_DCH089: SITE1.H20(PAD_PM_PWM3)
S1_DCH090: SITE1.A21(PAD_PM_SAR_GPIO1)
S1_DCH103: SITE1.E12(PAD_RTC_IO0)
S1_DCH104: SITE1.D12(PAD_RTC_IO1)
S1_DCH107: SITE1.E11(PAD_RESET) SW5.6
S1_DCH108: K32.2
S1_DCH109: K32.7
S1_DCH110: U449.3(MHL+)
S1_DCH111: U449.4(MHL-)
S1_DPS3: SW10.10 ; also on sheet 17
S1_DPS4: SW5.10 ; also on sheet 17
S1_M_2V5: C284.1 C285.1 MR2.1 MU2.6(VOUT)
S1_M_3V2: C282.1 C283.1 C289.1 MR1.1 MU1.5(Vout) MU2.2(VIN) MU3.7(V+)
S1_Mpdch01: SITE1.D7(PAD_I2C1_SDA)
S1_Mpdch03+: U31.2(D+)
S1_Mpdch03-: U31.3(D-)
S1_Mpdch05: SITE1.E7(PAD_I2C1_SCL)
S1_Mpdch06: SITE1.T4(PAD_SD0_D1)
S1_Mpdch09: SITE1.E8(PAD_SR_RST0)
S1_Mpdch10: SITE1.D8(PAD_SR_MCLK0)
S1_Mpdch11: SITE1.T3(PAD_SD0_CDZ)
S1_Mpdch13: SITE1.U4(PAD_SD0_D0)
S1_Mpdch14: SITE1.U5(PAD_SD0_CLK)
S1_Mpdch15: SITE1.T6(PAD_SD0_CMD)
S1_Mpdch16: SITE1.U7(PAD_SD0_D3)
S1_Mpdch17: SITE1.T7(PAD_SD0_D2)
S1_Mpdch18: SITE1.U20(PAD_FUART_RX)
S1_Mpdch19: SITE1.U21(PAD_FUART_TX)
S1_Mpdch20: SITE1.U18(PAD_FUART_RTS)
S1_Mpdch21: SITE1.R2(PAD_GPIO0)
S1_Mpdch22: SITE1.P6(PAD_GPIO5)
S1_Mpdch23: SITE1.R3(PAD_GPIO1)
S1_Mpdch24: SITE1.T2(PAD_GPIO10)
S1_Mpdch25: SITE1.R1(PAD_GPIO8)
S1_Mpdch26: SITE1.T1(PAD_GPIO9)
S1_Mpdch27: SITE1.P7(PAD_GPIO6)
S1_Mpdch28: SITE1.P4(PAD_GPIO3)
S1_Mpdch29: SITE1.U2(PAD_GPIO11)
S1_Mpdch30: SITE1.R7(PAD_GPIO7)
S1_Mpdch32: K2.2
S1_Mpdch33: SITE1.L2(PAD_AUD_MICIN1)
S1_Mpdch34: C264.1 SITE1.M3(PAD_AUD_VAG)
S1_Mpdch35: SITE1.N2(PAD_AUD_MICIN0)
S1_Mpdch36: SITE1.L20(PAD_I2C0_SDA)
S1_Mpdch49: SITE1.E5(PAD_SR_RST1)
S1_Mpdch50: SITE1.D5(PAD_SR_MCLK1)
S1_Mpdch51: SITE1.T18(PAD_FUART_CTS)
S1_Mpdch52: SITE1.T19(PAD_MSPI0_CZ)
S1_Mpdch53: SITE1.R4(PAD_GPIO2)
S1_Mpdch54: SITE1.P5(PAD_GPIO4)
S1_Mpdch55: SITE1.D4(PAD_I2C2_SCL)
S1_Mpdch56: SITE1.E4(PAD_I2C2_SDA)
S1_Mpdch57: SITE1.N19(PAD_MSPI0_CK)
S1_Mpdch58: SITE1.P19(PAD_MSPI0_DI)
S1_Mpdch59: SITE1.R19(PAD_MSPI0_DO)
S1_Mpdch60: SITE1.M20(PAD_I2C0_SCL)
S1_Mpdch61: SITE1.G21(PAD_PM_UART_RX)
S1_Mpdch62: SITE1.H22(PAD_PM_UART_TX)
S1_Mpdch63: SITE1.C19(PAD_PM_I2C_SDA)
S1_Mpdch64: SITE1.D19(PAD_PM_I2C_SCL)
S1_Mpdch65: SITE1.B22(PAD_PM_GPIO5)
S1_Mpdch66: SITE1.C22(PAD_PM_GPIO6)
S1_Mpdch68: SITE1.B21(PAD_PM_GPIO4)
S1_Mpdch69: SITE1.F19(PAD_PM_PWM1)
S1_Mpdch71: SITE1.H21(PAD_PM_GPIO11)
S1_Mpdch72: SITE1.E15(PAD_PM_FUART_RX)
S1_Mpdch73: SITE1.E18(PAD_PM_GPIO2)
S1_Mpdch74: SITE1.D18(PAD_PM_GPIO3)
S1_Mpdch75: SITE1.E22(PAD_PM_PSPI0_DO)
S1_Mpdch76: SITE1.F22(PAD_PM_PSPI0_DI)
S1_Mpdch77: SITE1.E19(PAD_PM_PWM0)
S1_Mpdch78: SITE1.C20(PAD_PM_UART2_RX)
S1_Mpdch79: SITE1.D20(PAD_PM_UART2_TX)
S1_Mpdch80: SITE1.E21(PAD_PM_PSPI0_CK)
S1_Mpdch81: SITE1.D21(PAD_PM_PSPI0_CZ)
S1_Mpdch84: SITE1.F21(PAD_PM_PSPI0_INT)
S1_Mpdch85: SITE1.E17(PAD_PM_GPIO1)
S1_Mpdch86: SITE1.C16(PAD_PM_GPIO0)
S1_Mpdch87: SITE1.E14(PAD_PM_FUART_TX)
S1_Mpdch88: K34.2
S1_MUX_3V3: BD21.1 BD1728.1 R512.1 ; also on sheet 18
S1_PM_SAR_GPIO0: K34.3 MK3.4 S1_VREF_OUT.1(TP) SITE1.A20(PAD_PM_SAR_GPIO0)
S1_PM_UART_RX: JP1.2
S1_PM_UART_TX: JP1.1
S1_SPI_CK_ABCD_CASE: K2.6 SITE1.T22(PAD_SPI_CK)
S1_SPI_CK_B_CASE: K2.5 K3.6
S1_SPI_CK_C_CASE: K3.7 U18.7(RESET#)
S1_SPI_CK_D_CASE: K3.5 U19.6
S1_SPI_CZ_ABCD_CASE: K2.3 SITE1.M21(PAD_SPI_CZ)
S1_SPI_CZ_B_CASE: K2.4 K3.3
S1_SPI_CZ_C_CASE: K3.2 R200.2 U18.1(CS#)
S1_SPI_CZ_D_CASE: K3.4 R205.2 U19.1
S1_SPI_DI_ABCD_CASE: K4.6 SITE1.R21(PAD_SPI_DI)
S1_SPI_DI_B_CASE: K4.5 K5.6
S1_SPI_DI_C_CASE: K5.7
S1_SPI_DI_D_CASE: K5.5 U19.5
S1_SPI_DO_ABCD_CASE: K4.3 SITE1.P22(PAD_SPI_DO)
S1_SPI_DO_B_CASE: K4.4 K5.3
S1_SPI_DO_C_CASE: K5.2
S1_SPI_DO_D_CASE: K5.4 U19.2
S1_SPI_HLD_ABCD_CASE: K6.3 SITE1.P21(PAD_SPI_HLD)
S1_SPI_HLD_B_CASE: K6.4 K7.3
S1_SPI_HLD_C_CASE: K7.2 R202.1
S1_SPI_HLD_D_CASE: K7.4 R206.1 U19.7
S1_SPI_WPZ_ABCD_CASE: K6.6 SITE1.N21(PAD_SPI_WPZ)
S1_SPI_WPZ_B_CASE: K6.5 K7.6
S1_SPI_WPZ_C_CASE: K7.7 R203.2 U18.2(SO)
S1_SPI_WPZ_D_CASE: K7.5 R207.2 U19.3
S1_USB2_SEL0: R164.2 U31.6(SEL0)
S1_USB2_SEL1: R163.2 U31.5(SEL1)
S1_USB2_SELS: R165.2 U31.16(SELS)
S1_USB_D_AB_CASE+: SITE1.J3(PAD_DP_USB) U31.10(HSD2+)
S1_USB_D_AB_CASE-: SITE1.J2(PAD_DM_USB) U31.9(HSD2-)
S1_USB_D_B_CASE+: R160.2 U31.8(HSD2S+)
S1_USB_D_B_CASE-: R161.2 U31.7(HSD2S-)
S1_USER_3V3: C334.1 C335.1 C336.2 C337.2 C338.2 C339.2 R200.1 R201.2 R202.2 R203.1 R204.2 R205.1 R206.2 R207.1 S1_USER_3V3.1 U17.3(Vout)
S1_XTAL_24M_IN_ABC_CASE: K32.3 SITE1.L22(PAD_XTAL_IN_24M)
S1_XTAL_24M_IN_B_CASE: K32.4 R135.1
S1_XTAL_24M_IN_C_CASE: C267.1 R135.2 R136.2 Y1.3
S1_XTAL_24M_OUT_ABC_CASE: K32.6 SITE1.K21(PAD_XTAL_OUT_24M)
S1_XTAL_24M_OUT_B_CASE: K32.5 R137.1
S1_XTAL_24M_OUT_C_CASE: C268.1 R136.1 R137.2 Y1.1
S1_XTAL_IN_32K_A_CASE: K29.7 U449.7(D-)
S1_XTAL_IN_32K_ABCD_CASE: K29.6 SITE1.B13(PAD_XTAL_IN_32K)
S1_XTAL_IN_32K_B_CASE: C271.1 K29.5 Y2.1
S1_XTAL_IN_32K_D_CASE: R923.1 R973.2 U449.2(USB-)
S1_XTAL_OUT_32K_A_CASE: K29.2 U449.8(D+)
S1_XTAL_OUT_32K_ABCD_CASE: K29.3 SITE1.A12(PAD_XTAL_OUT_32K)
S1_XTAL_OUT_32K_B_CASE: C272.1 K29.4 Y2.2
S1_XTAL_OUT_32K_D_CASE: R652.1 R973.1 U449.1(USB+)
S3_0V5: 3C286.1 3C288.1 3MK1.4 3MR2.2 3MR3.1 3MR4.1 3MR5.1 3MR6.1 3MU3.3(+IN)
S3_0V25: 3MK4.3 3MR18.2 3MR19.1
S3_0V75: 3C290.1 3MK2.4 3MR10.2 3MU3.6(OUT)
S3_1SPI_CK: 3K2.7
S3_1SPI_DI: 3K4.7
S3_1SPI_DO: 3K4.2
S3_1SPI_HLD: 3K6.2
S3_1SPI_WPZ: 3K6.7
S3_3V3_USB2_MUX: 3BD21.2 3C262.1 3U31.4(VCC)
S3_3V3_XTAL32K: 3BD1728.2 3C1074.1 3R981.1 3U449.10(VCC)
S3_AWG_3SHARE+: 3K34.4 ; also on sheet 20
S3_B_DCH105: SITE3.C12(PAD_RTC_IO4)
S3_B_DCH106: SITE3.D13(PAD_RTC_IO5)
S3_DCH015: SITE3.N1(PAD_AUD_MICCM0)
S3_DCH016: SITE3.L1(PAD_AUD_MICCM1)
S3_DCH017: SITE3.L3(PAD_AUD_LINEOUT_RP)
S3_DCH018: SITE3.L4(PAD_AUD_LINEOUT_RN)
S3_DCH063: SITE3.A17(PAD_PM_SDIO_CLK)
S3_DCH064: SITE3.B16(PAD_PM_SDIO_CMD)
S3_DCH065: SITE3.A18(PAD_PM_SDIO_D0)
S3_DCH066: SITE3.B18(PAD_PM_SDIO_D1)
S3_DCH067: SITE3.B15(PAD_PM_SDIO_D2)
S3_DCH068: SITE3.A15(PAD_PM_SDIO_D3)
S3_DCH069: SITE3.B19(PAD_PM_SDIO_INT)
S3_DCH082: SITE3.D15(PAD_PM_FUART_CTS)
S3_DCH083: SITE3.D16(PAD_PM_FUART_RTS)
S3_DCH088: SITE3.G20(PAD_PM_PWM2)
S3_DCH089: SITE3.H20(PAD_PM_PWM3)
S3_DCH090: SITE3.A21(PAD_PM_SAR_GPIO1)
S3_DCH103: SITE3.E12(PAD_RTC_IO0)
S3_DCH104: SITE3.D12(PAD_RTC_IO1)
S3_DCH107: SITE3.E11(PAD_RESET)
S3_DCH108: 3K32.2
S3_DCH109: 3K32.7
S3_DCH110: 3U449.3(MHL+)
S3_DCH111: 3U449.4(MHL-)
S3_M_2V5: 3C284.1 3C285.1 3MR2.1 3MU2.6(VOUT)
S3_M_3V2: 3C282.1 3C283.1 3C289.1 3MR1.1 3MU1.5(Vout) 3MU2.2(VIN) 3MU3.7(V+)
S3_Mpdch01: SITE3.D7(PAD_I2C1_SDA)
S3_Mpdch03+: 3U31.2(D+)
S3_Mpdch03-: 3U31.3(D-)
S3_Mpdch05: SITE3.E7(PAD_I2C1_SCL)
S3_Mpdch06: SITE3.T4(PAD_SD0_D1)
S3_Mpdch09: SITE3.E8(PAD_SR_RST0)
S3_Mpdch10: SITE3.D8(PAD_SR_MCLK0)
S3_Mpdch11: SITE3.T3(PAD_SD0_CDZ)
S3_Mpdch13: SITE3.U4(PAD_SD0_D0)
S3_Mpdch14: SITE3.U5(PAD_SD0_CLK)
S3_Mpdch15: SITE3.T6(PAD_SD0_CMD)
S3_Mpdch16: SITE3.U7(PAD_SD0_D3)
S3_Mpdch17: SITE3.T7(PAD_SD0_D2)
S3_Mpdch18: SITE3.U20(PAD_FUART_RX)
S3_Mpdch19: SITE3.U21(PAD_FUART_TX)
S3_Mpdch20: SITE3.U18(PAD_FUART_RTS)
S3_Mpdch21: SITE3.R2(PAD_GPIO0)
S3_Mpdch22: SITE3.P6(PAD_GPIO5)
S3_Mpdch23: SITE3.R3(PAD_GPIO1)
S3_Mpdch24: SITE3.T2(PAD_GPIO10)
S3_Mpdch25: SITE3.R1(PAD_GPIO8)
S3_Mpdch26: SITE3.T1(PAD_GPIO9)
S3_Mpdch27: SITE3.P7(PAD_GPIO6)
S3_Mpdch28: SITE3.P4(PAD_GPIO3)
S3_Mpdch29: SITE3.U2(PAD_GPIO11)
S3_Mpdch30: SITE3.R7(PAD_GPIO7)
S3_Mpdch32: 3K2.2
S3_Mpdch33: SITE3.L2(PAD_AUD_MICIN1)
S3_Mpdch34: 3C264.1 SITE3.M3(PAD_AUD_VAG)
S3_Mpdch35: SITE3.N2(PAD_AUD_MICIN0)
S3_Mpdch36: SITE3.L20(PAD_I2C0_SDA)
S3_Mpdch49: SITE3.E5(PAD_SR_RST1)
S3_Mpdch50: SITE3.D5(PAD_SR_MCLK1)
S3_Mpdch51: SITE3.T18(PAD_FUART_CTS)
S3_Mpdch52: SITE3.T19(PAD_MSPI0_CZ)
S3_Mpdch53: SITE3.R4(PAD_GPIO2)
S3_Mpdch54: SITE3.P5(PAD_GPIO4)
S3_Mpdch55: SITE3.D4(PAD_I2C2_SCL)
S3_Mpdch56: SITE3.E4(PAD_I2C2_SDA)
S3_Mpdch57: SITE3.N19(PAD_MSPI0_CK)
S3_Mpdch58: SITE3.P19(PAD_MSPI0_DI)
S3_Mpdch59: SITE3.R19(PAD_MSPI0_DO)
S3_Mpdch60: SITE3.M20(PAD_I2C0_SCL)
S3_Mpdch61: SITE3.G21(PAD_PM_UART_RX)
S3_Mpdch62: SITE3.H22(PAD_PM_UART_TX)
S3_Mpdch63: SITE3.C19(PAD_PM_I2C_SDA)
S3_Mpdch64: SITE3.D19(PAD_PM_I2C_SCL)
S3_Mpdch65: SITE3.B22(PAD_PM_GPIO5)
S3_Mpdch66: SITE3.C22(PAD_PM_GPIO6)
S3_Mpdch68: SITE3.B21(PAD_PM_GPIO4)
S3_Mpdch69: SITE3.F19(PAD_PM_PWM1)
S3_Mpdch71: SITE3.H21(PAD_PM_GPIO11)
S3_Mpdch72: SITE3.E15(PAD_PM_FUART_RX)
S3_Mpdch73: SITE3.E18(PAD_PM_GPIO2)
S3_Mpdch74: SITE3.D18(PAD_PM_GPIO3)
S3_Mpdch75: SITE3.E22(PAD_PM_PSPI0_DO)
S3_Mpdch76: SITE3.F22(PAD_PM_PSPI0_DI)
S3_Mpdch77: SITE3.E19(PAD_PM_PWM0)
S3_Mpdch78: SITE3.C20(PAD_PM_UART2_RX)
S3_Mpdch79: SITE3.D20(PAD_PM_UART2_TX)
S3_Mpdch80: SITE3.E21(PAD_PM_PSPI0_CK)
S3_Mpdch81: SITE3.D21(PAD_PM_PSPI0_CZ)
S3_Mpdch84: SITE3.F21(PAD_PM_PSPI0_INT)
S3_Mpdch85: SITE3.E17(PAD_PM_GPIO1)
S3_Mpdch86: SITE3.C16(PAD_PM_GPIO0)
S3_Mpdch87: SITE3.E14(PAD_PM_FUART_TX)
S3_Mpdch88: 3K34.2
S3_MUX_3V3: 3BD21.1 3BD1728.1 3R512.1 ; also on sheet 11
S3_PM_SAR_GPIO0: 3K34.3 3MK3.4 S3_VREF_OUT.1(TP) SITE3.A20(PAD_PM_SAR_GPIO0)
S3_SPI_CK_ABCD_CASE: 3K2.6 SITE3.T22(PAD_SPI_CK)
S3_SPI_CK_B_CASE: 3K2.5 3K3.6
S3_SPI_CK_C_CASE: 3K3.7 3U18.7(RESET#)
S3_SPI_CK_D_CASE: 3K3.5 3U19.6
S3_SPI_CZ_ABCD_CASE: 3K2.3 SITE3.M21(PAD_SPI_CZ)
S3_SPI_CZ_B_CASE: 3K2.4 3K3.3
S3_SPI_CZ_C_CASE: 3K3.2 3R200.2 3U18.1(CS#)
S3_SPI_CZ_D_CASE: 3K3.4 3R205.2 3U19.1
S3_SPI_DI_ABCD_CASE: 3K4.6 SITE3.R21(PAD_SPI_DI)
S3_SPI_DI_B_CASE: 3K4.5 3K5.6
S3_SPI_DI_C_CASE: 3K5.7
S3_SPI_DI_D_CASE: 3K5.5 3U19.5
S3_SPI_DO_ABCD_CASE: 3K4.3 SITE3.P22(PAD_SPI_DO)
S3_SPI_DO_B_CASE: 3K4.4 3K5.3
S3_SPI_DO_C_CASE: 3K5.2
S3_SPI_DO_D_CASE: 3K5.4 3U19.2
S3_SPI_HLD_ABCD_CASE: 3K6.3 SITE3.P21(PAD_SPI_HLD)
S3_SPI_HLD_B_CASE: 3K6.4 3K7.3
S3_SPI_HLD_C_CASE: 3K7.2 3R202.1
S3_SPI_HLD_D_CASE: 3K7.4 3R206.1 3U19.7
S3_SPI_WPZ_ABCD_CASE: 3K6.6 SITE3.N21(PAD_SPI_WPZ)
S3_SPI_WPZ_B_CASE: 3K6.5 3K7.6
S3_SPI_WPZ_C_CASE: 3K7.7 3R203.2 3U18.2(SO)
S3_SPI_WPZ_D_CASE: 3K7.5 3R207.2 3U19.3
S3_USB2_SEL0: 3R164.2 3U31.6(SEL0)
S3_USB2_SEL1: 3R163.2 3U31.5(SEL1)
S3_USB2_SELS: 3R165.2 3U31.16(SELS)
S3_USB_D_AB_CASE+: 3U31.10(HSD2+) SITE3.J3(PAD_DP_USB)
S3_USB_D_AB_CASE-: 3U31.9(HSD2-) SITE3.J2(PAD_DM_USB)
S3_USB_D_B_CASE+: 3R160.2 3U31.8(HSD2S+)
S3_USB_D_B_CASE-: 3R161.2 3U31.7(HSD2S-)
S3_USER_3V3: 3C334.1 3C335.1 3C336.2 3C337.2 3C338.2 3C339.2 3R200.1 3R201.2 3R202.2 3R203.1 3R204.2 3R205.1 3R206.2 3R207.1 3U17.3(Vout) S3_USER_3V3.1
S3_XTAL_24M_IN_ABC_CASE: 3K32.3 SITE3.L22(PAD_XTAL_IN_24M)
S3_XTAL_24M_IN_B_CASE: 3K32.4 3R135.1
S3_XTAL_24M_IN_C_CASE: 3C267.1 3R135.2 3R136.2 3Y1.3
S3_XTAL_24M_OUT_ABC_CASE: 3K32.6 SITE3.K21(PAD_XTAL_OUT_24M)
S3_XTAL_24M_OUT_B_CASE: 3K32.5 3R137.1
S3_XTAL_24M_OUT_C_CASE: 3C268.1 3R136.1 3R137.2 3Y1.1
S3_XTAL_IN_32K_A_CASE: 3K29.7 3U449.7(D-)
S3_XTAL_IN_32K_ABCD_CASE: 3K29.6 SITE3.B13(PAD_XTAL_IN_32K)
S3_XTAL_IN_32K_B_CASE: 3C271.1 3K29.5 3Y2.1
S3_XTAL_IN_32K_D_CASE: 3R923.1 3R973.2 3U449.2(USB-)
S3_XTAL_OUT_32K_A_CASE: 3K29.2 3U449.8(D+)
S3_XTAL_OUT_32K_ABCD_CASE: 3K29.3 SITE3.A12(PAD_XTAL_OUT_32K)
S3_XTAL_OUT_32K_B_CASE: 3C272.1 3K29.4 3Y2.2
S3_XTAL_OUT_32K_D_CASE: 3R652.1 3R973.1 3U449.1(USB+)
SA_CBIT_R2: K2.8(V-)
SA_CBIT_R3: K3.8(V-)
SA_CBIT_R4: K4.8(V-)
SA_CBIT_R5: K5.8(V-)
SA_CBIT_R6: K6.8(V-)
SA_CBIT_R7: K7.8(V-)
SA_CBIT_R29: K29.8(V-)
SA_CBIT_R32: K32.8(V-)
SA_CBIT_R34: K34.8(V-)
SA_CBIT_S01: R163.1
SA_CBIT_S02: R164.1
SA_CBIT_S03: R165.1
SA_CBIT_S25: MK1.2(V-) MR12.2
SA_CBIT_S26: MK2.2(V-) MR15.2
SA_CBIT_S27: MK4.2(V-) MR17.2
SA_CBIT_S28: MK3.2(V-)
SA_CBIT_S97: R982.1
UT1_UP5V: 3C278.1 3C279.1 3C280.1 3C281.1 3C332.1 3C333.1 3C476.1 3C477.1 3C478.1 3K2.1(V+) 3K3.1(V+) 3K4.1(V+) 3K5.1(V+) 3K6.1(V+) 3K7.1(V+) 3K29.1(V+) 3K32.1(V+) 3K34.1(V+) 3MBD1.1 3MR11.1 3MR12.1 3MR13.1 3MR14.2 3MR15.1 3MR16.1 3MR17.1 3MU1.1(Vin) 3MU1.3(EN) 3R331.1 3R509.2 3U17.2(Vin) 3U108.4(VDD) C278.1 C279.1 C280.1 C281.1 C332.1 C333.1 C476.1 C477.1 C478.1 K2.1(V+) K3.1(V+) K4.1(V+) K5.1(V+) K6.1(V+) K7.1(V+) K29.1(V+) K32.1(V+) K34.1(V+) MBD1.1 MR11.1 MR12.1 MR13.1 MR14.2 MR15.1 MR16.1 MR17.1 MU1.1(Vin) MU1.3(EN) R331.1 R509.2 U17.2(Vin) U108.4(VDD) ; also on sheet 2 4 6 8 10 12 14 17 19 20 21 22 23 24 25 26 27 28 32 33 34 35 36 37
N21055971: R162.1 U31.15(OE#)
N21056737: R510.2 R511.1 U108.1(ADJ)
N21056761: C475.1 R510.1 R512.2 TP_MUX_3V3.1(TP) U108.5(VOUT)
N21056763: R509.1 U108.3(CE)
N21136265: BD9.1 SITE1.N3(PAD_AUD_VRM)
N21140049: MU4.3(EN) R331.2
N21140128: C299.2 MU4.1(FILTER)
N21140130: C300.1 C301.1 MR18.1 MU4.5(OUTS) MU4.6(OUTF)
N21140140: C298.2 MBD1.2 MU4.4(IN)
N21140206: MR1.2 MR7.2 MU1.4(FB)
N21140226: MR8.1 MR9.1 MU3.2(-IN)
N21140298: MK2.1(V+) MR13.2
N21140308: MK1.3 MK2.3 MK3.3 MK4.4
N21140322: MK3.1(V+) MR14.1
N21140329: MK4.1(V+) MR16.2
N21140374: MR9.2 MR10.1
N21140376: MK1.1(V+) MR11.2
N21514150: R980.1 U449.6(OE#)
N21514171: R981.2 R982.2 U449.9(SEL)
N21593930: R204.1 U19.8
N21594042: R201.1 U18.8(VCC)
N22566266: 3R162.1 3U31.15(OE#)
N22566291: 3R510.2 3R511.1 3U108.1(ADJ)
N22566297: 3C475.1 3R510.1 3R512.2 3TP_MUX_3V3.1(TP) 3U108.5(VOUT)
N22566298: 3R509.1 3U108.3(CE)
N22566594: 3BD9.1 SITE3.N3(PAD_AUD_VRM)
N22566598: 3MU4.3(EN) 3R331.2
N22566632: 3C299.2 3MU4.1(FILTER)
N22566633: 3C300.1 3C301.1 3MR18.1 3MU4.5(OUTS) 3MU4.6(OUTF)
N22566638: 3C298.2 3MBD1.2 3MU4.4(IN)
N22566667: 3MR1.2 3MR7.2 3MU1.4(FB)
N22566677: 3MR8.1 3MR9.1 3MU3.2(-IN)
N22566714: 3MK2.1(V+) 3MR13.2
N22566719: 3MK1.3 3MK2.3 3MK3.3 3MK4.4
N22566726: 3MK3.1(V+) 3MR14.1
N22566730: 3MK4.1(V+) 3MR16.2
N22566751: 3MR9.2 3MR10.1
N22566752: 3MK1.1(V+) 3MR11.2
N22566920: 3R980.1 3U449.6(OE#)
N22566931: 3R981.2 3R982.2 3U449.9(SEL)
N22567053: 3R204.1 3U19.8
N22567073: 3R201.1 3U18.8(VCC)

Not connected (* = marked no-connect by the designer): 3K34 5* 6* 7*; 3MU2 1(NC1)* 3(NC2)* 5(NC3)* 7(NC4)* 8(TP)*; 3MU3 1(NC1)* 5(NC2)* 8(NC3)*; 3U18 3(WP#) 4(GND) 5(SI) 6(SCLK); 3U19 GH1* GH2*; 3U31 11(HSD1+)* 12(HSD1-)* 13(HSD0+)* 14(HSD0-)*; JP1 4 NC1 NC2; K34 5* 6* 7*; MU2 1(NC1)* 3(NC2)* 5(NC3)* 7(NC4)* 8(TP)*; MU3 1(NC1)* 5(NC2)* 8(NC3)*; SITE1 A1(NC[0])* A3(NC[1])* A5(NC[2])* A7(NC[3])* A9(NC[4])* A11(NC[5])* A13(NC[6])* A14(NC[7])* A16(NC[8])* A19(NC[9])* A22(NC[10])* C5(NC[11])* C7(NC[12])* C9(NC[13])* C13(NC[14])* C18(NC[15])* C21(NC[16])* D1(NC[17])* D6(NC[18])* D9(NC[19])* D10(NC[20])* D11(NC[21])* D14(NC[22])* D17(NC[23])* D22(NC[24])* E6(NC[25])* E9(NC[26])* E13(NC[27])* E16(NC[28])* F1(NC[29])* F5(NC[30])* F11(NC[31])* F14(NC[32])* F16(NC[33])* F18(NC[34])* F20(NC[35])* G4(NC[36])* G19(NC[37])* G22(NC[38])* H1(NC[39])* H3(NC[40])* H5(NC[41])* H18(NC[42])* J1(NC[43])* J4(NC[44])* J19(NC[45])* J22(NC[46])* K1(NC[47])* K2(NC[48])* K3(NC[49])* K5(NC[50])* K18(NC[51])* K20(NC[52])* K22(NC[53])* L19(NC[54])* M1(NC[55])* M5(NC[56])* M19(NC[57])* M22(NC[58])* N4(NC[59])* N5(NC[60])* N18(NC[61])* N22(NC[62])* NGH1* NGH2* NGH3* NGH4* NUT1* NUT2* NUT3* NUT4* P1(NC[63])* P20(NC[64])* R5(NC[65])* R6(NC[66])* R10(NC[67])* R12(NC[68])* R13(NC[69])* R20(NC[70])* R22(NC[71])* T12(NC[72])* T20(NC[73])* U1(NC[74])* U3(NC[75])* U6(NC[76])* U8(NC[77])* U10(NC[78])* U12(NC[79])* U14(NC[80])* U17(NC[81])* U19(NC[82])* U22(NC[83])*; SITE3 A1(NC[0])* A3(NC[1])* A5(NC[2])* A7(NC[3])* A9(NC[4])* A11(NC[5])* A13(NC[6])* A14(NC[7])* A16(NC[8])* A19(NC[9])* A22(NC[10])* C5(NC[11])* C7(NC[12])* C9(NC[13])* C13(NC[14])* C18(NC[15])* C21(NC[16])* D1(NC[17])* D6(NC[18])* D9(NC[19])* D10(NC[20])* D11(NC[21])* D14(NC[22])* D17(NC[23])* D22(NC[24])* E6(NC[25])* E9(NC[26])* E13(NC[27])* E16(NC[28])* F1(NC[29])* F5(NC[30])* F11(NC[31])* F14(NC[32])* F16(NC[33])* F18(NC[34])* F20(NC[35])* G4(NC[36])* G19(NC[37])* G22(NC[38])* H1(NC[39])* H3(NC[40])* H5(NC[41])* H18(NC[42])* J1(NC[43])* J4(NC[44])* J19(NC[45])* J22(NC[46])* K1(NC[47])* K2(NC[48])* K3(NC[49])* K5(NC[50])* K18(NC[51])* K20(NC[52])* K22(NC[53])* L19(NC[54])* M1(NC[55])* M5(NC[56])* M19(NC[57])* M22(NC[58])* N4(NC[59])* N5(NC[60])* N18(NC[61])* N22(NC[62])* NGH1* NGH2* NGH3* NGH4* NUT1* NUT2* NUT3* NUT4* P1(NC[63])* P20(NC[64])* R5(NC[65])* R6(NC[66])* R10(NC[67])* R12(NC[68])* R13(NC[69])* R20(NC[70])* R22(NC[71])* T12(NC[72])* T20(NC[73])* U1(NC[74])* U3(NC[75])* U6(NC[76])* U8(NC[77])* U10(NC[78])* U12(NC[79])* U14(NC[80])* U17(NC[81])* U19(NC[82])* U22(NC[83])*; SW5 1* 2* 3* 4* 5* 7* 8*; SW10 6* 7* 8*; U18 3(WP#) 4(GND) 5(SI) 6(SCLK); U19 GH1* GH2*; U31 11(HSD1+)* 12(HSD1-)* 13(HSD0+)* 14(HSD0-)*

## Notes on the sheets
sheet 30
- USB 2.0
- Close to DUT
- USB¡BAUD
- DIFF 90 ohm
- 3.3V
- XTAL
- PAD_RTC_IO4~5: Use wider traces.
- XTAL_24M
- USB DC MUX:
- Close to DUT
- FSUSB73UMX-UMLP16
  RON (Typical): 6.5 £[
- SEL1
- SEL0
- Function
- (mUbit7)
- (mUbit8)
- 0
- 1
- NA
- 1
- 0
- NA
- 1
- 1
- USB DC(default)
- Trace Width: 20 mil
- Close to DUT
- SELS
- Function
- XTAL_32K
- (mUbit9)
- 1
- R_ON(default)
- Close to DUT
- 0
- R_OFF
- Close to DUT
- Connect the bead directly to GND.
- apply GND shielding.
- PAD_PM_GPIO3~5: Use wider traces
- GND
- SPI FLASH
- FLASH
- NOR
- NAND
- CS#
- VCC
- 8
- DO/IO1
- HOLD#/RST#IO3
- WP#/IO2
- SCLK
- GND
- DI/IO0
- 4
- 5
- NOR¡GW25Q128JVSIQ-SOIC8
  NAND¡GW25N01GVZEIG
- Please measure the output voltage before shipment.
  (1)0.25V +/-1% (0.2475~0.2525V)
  (2)0.5V +/-1% (0.495~0.505V)
  (3)0.75V +/-1% (0.7425~0.7575V)
- SAR_GPIO0: Precise voltage levels of 0.25 V / 0.5 V / 0.75 V.
- Vout=0.5*(1+499/1K)=0.7495V
- NO
- NO
- NC
- supply current 0.235mA
- VOUT = 3 V (fixed by part number). Max. output current: ¡Ó10 mA.
- High-precision 0.25 V reference voltage source (V0 = 3 V ¡Ñ [1K / 12K] = 0.25 V).
- Relay (CH, AWG, SAR_GPIO0): Provide precision voltage levels of 0.25 V / 0.5 V / 0.75 V.
- Connect the precision voltage source before the relay.
- MCB Assign: Only channels A¡VD are allowed.
  Channels can be interchanged.
- AWG
- Use copper shapes for all connections from DUT to MK3.
  Ensure consistency across all SITES.
- Relay~ AWG Apply GND shielding.
sheet 31
- USB 2.0
- Close to DUT
- USB¡BAUD
- DIFF 90 ohm
- 3.3V
- XTAL
- PAD_RTC_IO4~5: Use wider traces.
- XTAL_24M
- USB DC MUX:
- Close to DUT
- FSUSB73UMX-UMLP16
  RON (Typical): 6.5 £[
- SEL1
- SEL0
- Function
- (mUbit7)
- (mUbit8)
- 0
- 1
- NA
- 1
- 0
- NA
- 1
- 1
- USB DC(default)
- Trace Width: 20 mil
- Close to DUT
- SELS
- Function
- XTAL_32K
- (mUbit9)
- 1
- R_ON(default)
- Close to DUT
- 0
- R_OFF
- Close to DUT
- Connect the bead directly to GND.
- apply GND shielding.
- PAD_PM_GPIO3~5: Use wider traces
- GND¡BNC
- SPI FLASH
- FLASH
- NOR
- NAND
- CS#
- VCC
- 8
- DO/IO1
- HOLD#/RST#IO3
- WP#/IO2
- SCLK
- GND
- DI/IO0
- 4
- 5
- NOR¡GW25Q128JVSIQ-SOIC8
  NAND¡GW25N01GVZEIG
- Debug Board
- Please measure the output voltage before shipment.
  (1)0.25V +/-1% (0.2475~0.2525V)
  (2)0.5V +/-1% (0.495~0.505V)
  (3)0.75V +/-1% (0.7425~0.7575V)
- SAR_GPIO0: Precise voltage levels of 0.25 V / 0.5 V / 0.75 V.
- I2C
- 3.3V
- 1.8V
- Vout=0.5*(1+499/1K)=0.7495V
- NO
- Please add text labels on the PCB.
- Please add text labels on the PCB.
- NO
- NC
- supply current 0.235mA
- VOUT = 3 V (fixed by part number). Max. output current: ¡Ó10 mA.
- High-precision 0.25 V reference voltage source (V0 = 3 V ¡Ñ [1K / 12K] = 0.25 V).
- Relay (CH, AWG, SAR_GPIO0): Provide precision voltage levels of 0.25 V / 0.5 V / 0.75 V.
- Connect the precision voltage source before the relay.
- MCB Assign: Only channels A¡VD are allowed.
  Channels can be interchanged.
- AWG
- Use copper shapes for all connections from DUT to MK3.
  Ensure consistency across all SITES.
- Relay~ AWG Apply GND shielding.
